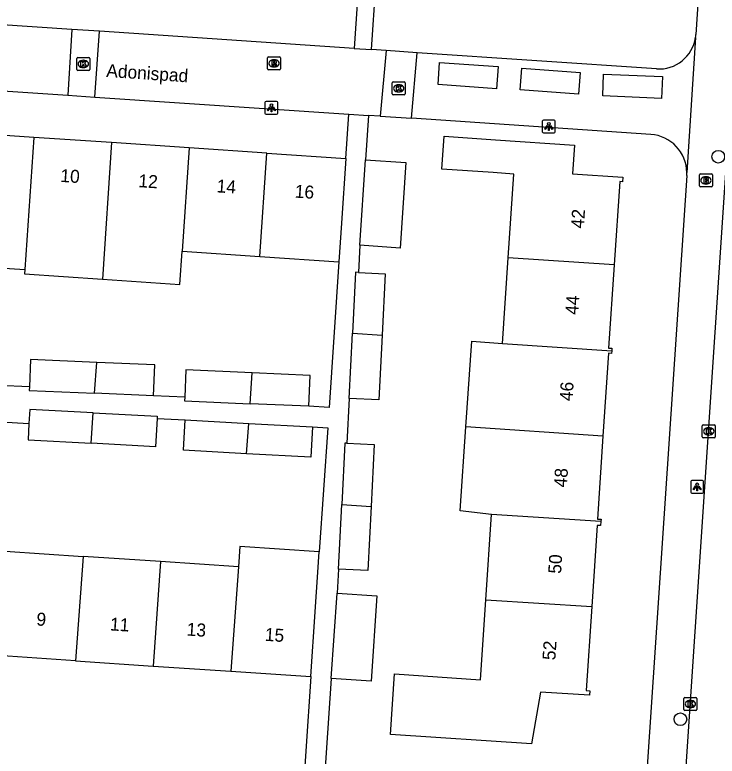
# Model space of a CAD drawing. Extents: x 161848 to 162726, y 385382 to 386521.
# Drawn here: x 162081 to 162135.2, y 385812.1 to 385869.2 of the extents above; entities that cross this region are included whole.
import ezdxf

# ---------------------------------------------------------------- set-up
doc = ezdxf.new("R2010")
doc.units = 0
for name, color, linetype in [('IMGEO_Boom', 7, 'Continuous'), ('IMGEO_Brandkraan', 7, 'Continuous'), ('IMGEO_Kolk', 7, 'Continuous'), ('IMGEO_Lichtpunt', 7, 'Continuous'), ('IMGEO_Openbare_ruimte_label', 7, 'Continuous'), ('IMGEO_Pand', 7, 'Continuous'), ('IMGEO_Pand_nummerreeks', 7, 'Continuous'), ('IMGEO_Parkeervlak_open', 7, 'Continuous'), ('IMGEO_Rijbaan_lokaal_open', 7, 'Continuous'), ('IMGEO_Rioolput', 7, 'Continuous'), ('IMGEO_Voetpad_open', 7, 'Continuous'), ('IMGEO_Woonerf_open', 7, 'Continuous')]:
    doc.layers.add(name, color=color, linetype=linetype)

msp = doc.modelspace()

# ---------------------------------------------------------------- linework, layer by layer
at = {"layer": 'IMGEO_Boom'}
for centre in [(162135.242, 385858.291), (162132.321, 385814.921)]:
    msp.add_circle(centre, 0.489, dxfattribs=at)
at = {"layer": 'IMGEO_Brandkraan'}
for p, q in [((162133.785, 385856.036), (162133.785, 385856.888)), ((162133.86, 385856.962), (162134.712, 385856.962)), ((162134.273, 385856.742), (162134.298, 385856.742)), ((162134.786, 385856.888), (162134.786, 385856.036)), ((162134.296, 385856.182), (162134.271, 385856.182)), ((162134.712, 385855.962), (162133.86, 385855.962))]:
    msp.add_line(p, q, dxfattribs=at)
for points in [[(162133.785, 385856.036), (162133.785, 385856.888)], [(162133.86, 385856.962), (162134.712, 385856.962)], [(162134.133, 385856.662), (162134.133, 385856.262), (162134.346, 385856.262)], [(162134.364, 385856.662), (162134.133, 385856.662)], [(162134.312, 385856.581), (162134.258, 385856.581), (162134.258, 385856.505)], [(162134.786, 385856.888), (162134.786, 385856.036)], [(162134.258, 385856.505), (162134.311, 385856.505)], [(162134.32, 385856.429), (162134.258, 385856.429), (162134.258, 385856.348)], [(162134.258, 385856.348), (162134.32, 385856.348)], [(162134.712, 385855.962), (162133.86, 385855.962)]]:
    msp.add_lwpolyline(points, dxfattribs=at)
for centre, radius, start, end in [((162133.862, 385856.886), 0.0765, 91.552, 178.448), ((162133.862, 385856.886), 0.0765, 91.552, 178.448), ((162134.313, 385856.543), 0.0379, 267.8285, 90.9355), ((162134.368, 385856.517), 0.145, 59.4692, 91.5367), ((162134.393, 385856.564), 0.0922, 285.5137, 58.1501), ((162134.71, 385856.886), 0.0765, 1.552, 88.448), ((162134.71, 385856.886), 0.0765, 1.552, 88.448), ((162133.862, 385856.038), 0.0765, 181.552, 268.448), ((162133.862, 385856.038), 0.0765, 181.552, 268.448), ((162134.321, 385856.388), 0.0404, 269.8759, 90.5077), ((162134.352, 385856.513), 0.251, 268.6676, 293.5347), ((162134.398, 385856.372), 0.105, 301.3115, 78.989), ((162134.71, 385856.038), 0.0765, 271.552, 358.448), ((162134.71, 385856.038), 0.0765, 271.552, 358.448)]:
    msp.add_arc(centre, radius, start, end, dxfattribs=at)
for centre, major_axis, ratio, start_param, end_param in [((162134.272, 385856.462), (-0.387, 0.002), 0.722429, 4.712389, 7.853982), ((162134.297, 385856.462), (-0.39, 0.002), 0.717154, 1.570796, 4.712389)]:
    msp.add_ellipse(centre, major_axis=major_axis, ratio=ratio, start_param=start_param, end_param=end_param, dxfattribs=at)
at = {"layer": 'IMGEO_Kolk'}
for p, q in [((162085.78, 385865.022), (162085.78, 385865.874)), ((162085.855, 385865.948), (162086.707, 385865.948)), ((162086.268, 385865.728), (162086.293, 385865.728)), ((162086.781, 385865.874), (162086.781, 385865.022)), ((162086.291, 385865.168), (162086.266, 385865.168)), ((162086.707, 385864.948), (162085.855, 385864.948)), ((162110.098, 385863.135), (162110.098, 385863.987)), ((162110.173, 385864.061), (162111.025, 385864.061)), ((162111.099, 385863.987), (162111.099, 385863.135)), ((162110.586, 385863.841), (162110.611, 385863.841)), ((162111.025, 385863.061), (162110.173, 385863.061)), ((162110.609, 385863.281), (162110.584, 385863.281)), ((162134.009, 385836.687), (162134.009, 385837.539)), ((162134.084, 385837.613), (162134.936, 385837.613)), ((162134.497, 385837.393), (162134.522, 385837.393)), ((162135.01, 385837.539), (162135.01, 385836.687)), ((162134.936, 385836.613), (162134.084, 385836.613)), ((162134.52, 385836.833), (162134.495, 385836.833)), ((162132.667, 385816.59), (162133.519, 385816.59)), ((162132.592, 385815.664), (162132.592, 385816.516)), ((162133.08, 385816.37), (162133.105, 385816.37)), ((162133.593, 385816.516), (162133.593, 385815.664)), ((162133.519, 385815.59), (162132.667, 385815.59)), ((162133.103, 385815.81), (162133.078, 385815.81))]:
    msp.add_line(p, q, dxfattribs=at)
for points in [[(162085.78, 385865.022), (162085.78, 385865.874)], [(162085.855, 385865.948), (162086.707, 385865.948)], [(162086.781, 385865.874), (162086.781, 385865.022)], [(162086.101, 385865.648), (162086.224, 385865.648), (162086.224, 385865.497), (162086.354, 385865.648), (162086.518, 385865.648), (162086.372, 385865.497), (162086.525, 385865.248), (162086.373, 385865.248), (162086.288, 385865.412), (162086.224, 385865.345), (162086.224, 385865.248), (162086.101, 385865.248), (162086.101, 385865.648)], [(162086.707, 385864.948), (162085.855, 385864.948)], [(162110.098, 385863.135), (162110.098, 385863.987)], [(162110.173, 385864.061), (162111.025, 385864.061)], [(162111.099, 385863.987), (162111.099, 385863.135)], [(162110.419, 385863.761), (162110.542, 385863.761), (162110.542, 385863.61), (162110.672, 385863.761), (162110.836, 385863.761), (162110.69, 385863.61), (162110.843, 385863.361), (162110.691, 385863.361), (162110.606, 385863.525), (162110.542, 385863.458), (162110.542, 385863.361), (162110.419, 385863.361), (162110.419, 385863.761)], [(162111.025, 385863.061), (162110.173, 385863.061)], [(162134.009, 385836.687), (162134.009, 385837.539)], [(162134.084, 385837.613), (162134.936, 385837.613)], [(162134.33, 385837.313), (162134.453, 385837.313), (162134.453, 385837.162), (162134.583, 385837.313), (162134.747, 385837.313), (162134.601, 385837.162), (162134.754, 385836.913), (162134.602, 385836.913), (162134.517, 385837.077), (162134.453, 385837.01), (162134.453, 385836.913), (162134.33, 385836.913), (162134.33, 385837.313)], [(162135.01, 385837.539), (162135.01, 385836.687)], [(162134.936, 385836.613), (162134.084, 385836.613)], [(162132.667, 385816.59), (162133.519, 385816.59)], [(162132.592, 385815.664), (162132.592, 385816.516)], [(162132.913, 385816.29), (162133.036, 385816.29), (162133.036, 385816.139), (162133.166, 385816.29), (162133.33, 385816.29), (162133.184, 385816.139), (162133.337, 385815.89), (162133.185, 385815.89), (162133.1, 385816.054), (162133.036, 385815.987), (162133.036, 385815.89), (162132.913, 385815.89), (162132.913, 385816.29)], [(162133.593, 385816.516), (162133.593, 385815.664)], [(162133.519, 385815.59), (162132.667, 385815.59)]]:
    msp.add_lwpolyline(points, dxfattribs=at)
for centre, start, end in [((162085.857, 385865.872), 91.552, 178.448), ((162085.857, 385865.872), 91.552, 178.448), ((162086.705, 385865.872), 1.552, 88.448), ((162086.705, 385865.872), 1.552, 88.448), ((162085.857, 385865.024), 181.552, 268.448), ((162085.857, 385865.024), 181.552, 268.448), ((162086.705, 385865.024), 271.552, 358.448), ((162086.705, 385865.024), 271.552, 358.448), ((162110.175, 385863.985), 91.552, 178.448), ((162110.175, 385863.985), 91.552, 178.448), ((162111.023, 385863.985), 1.552, 88.448), ((162111.023, 385863.985), 1.552, 88.448), ((162110.175, 385863.137), 181.552, 268.448), ((162110.175, 385863.137), 181.552, 268.448), ((162111.023, 385863.137), 271.552, 358.448), ((162111.023, 385863.137), 271.552, 358.448), ((162134.086, 385837.537), 91.552, 178.448), ((162134.086, 385837.537), 91.552, 178.448), ((162134.934, 385837.537), 1.552, 88.448), ((162134.934, 385837.537), 1.552, 88.448), ((162134.086, 385836.689), 181.552, 268.448), ((162134.086, 385836.689), 181.552, 268.448), ((162134.934, 385836.689), 271.552, 358.448), ((162134.934, 385836.689), 271.552, 358.448), ((162132.669, 385816.514), 91.552, 178.448), ((162132.669, 385816.514), 91.552, 178.448), ((162133.517, 385816.514), 1.552, 88.448), ((162133.517, 385816.514), 1.552, 88.448), ((162132.669, 385815.666), 181.552, 268.448), ((162132.669, 385815.666), 181.552, 268.448), ((162133.517, 385815.666), 271.552, 358.448), ((162133.517, 385815.666), 271.552, 358.448)]:
    msp.add_arc(centre, 0.0765, start, end, dxfattribs=at)
for centre, major_axis, ratio, start_param, end_param in [((162086.267, 385865.448), (-0.387, 0.002), 0.722429, 4.712389, 7.853982), ((162086.292, 385865.448), (-0.39, 0.002), 0.717154, 1.570796, 4.712389), ((162110.585, 385863.561), (-0.387, 0.002), 0.722429, 4.712389, 7.853982), ((162110.61, 385863.561), (-0.39, 0.002), 0.717154, 1.570796, 4.712389), ((162134.496, 385837.113), (-0.387, 0.002), 0.722429, 4.712389, 7.853982), ((162134.521, 385837.113), (-0.39, 0.002), 0.717154, 1.570796, 4.712389), ((162133.079, 385816.09), (-0.387, 0.002), 0.722429, 4.712389, 7.853982), ((162133.104, 385816.09), (-0.39, 0.002), 0.717154, 1.570796, 4.712389)]:
    msp.add_ellipse(centre, major_axis=major_axis, ratio=ratio, start_param=start_param, end_param=end_param, dxfattribs=at)
at = {"layer": 'IMGEO_Lichtpunt'}
for p, q in [((162100.284, 385862.463), (162100.284, 385861.656)), ((162100.284, 385862.463), (162100.284, 385861.656)), ((162101.186, 385862.558), (162100.378, 385862.558)), ((162101.186, 385862.558), (162100.378, 385862.558)), ((162101.28, 385861.656), (162101.28, 385862.463)), ((162101.28, 385861.656), (162101.28, 385862.463)), ((162100.378, 385861.562), (162101.186, 385861.562)), ((162100.378, 385861.562), (162101.186, 385861.562)), ((162122.575, 385861.119), (162121.767, 385861.119)), ((162122.575, 385861.119), (162121.767, 385861.119)), ((162121.673, 385861.024), (162121.673, 385860.217)), ((162121.673, 385861.024), (162121.673, 385860.217)), ((162122.669, 385860.217), (162122.669, 385861.024)), ((162122.669, 385860.217), (162122.669, 385861.024)), ((162121.767, 385860.123), (162122.575, 385860.123)), ((162121.767, 385860.123), (162122.575, 385860.123)), ((162133.114, 385833.238), (162133.114, 385832.431)), ((162133.114, 385833.238), (162133.114, 385832.431)), ((162134.016, 385833.333), (162133.208, 385833.333)), ((162134.016, 385833.333), (162133.208, 385833.333)), ((162134.11, 385832.431), (162134.11, 385833.238)), ((162134.11, 385832.431), (162134.11, 385833.238)), ((162133.208, 385832.337), (162134.016, 385832.337)), ((162133.208, 385832.337), (162134.016, 385832.337))]:
    msp.add_line(p, q, dxfattribs=at)
for points in [[(162100.658, 385862.127), (162100.697, 385862.099), (162100.509, 385861.837), (162100.471, 385861.864), (162100.658, 385862.127)], [(162100.76, 385862.079), (162100.807, 385862.079), (162100.807, 385861.757), (162100.76, 385861.757), (162100.76, 385862.079)], [(162100.87, 385862.099), (162100.908, 385862.126), (162101.095, 385861.864), (162101.056, 385861.836), (162100.87, 385862.099)], [(162122.047, 385860.688), (162122.086, 385860.66), (162121.898, 385860.398), (162121.86, 385860.425), (162122.047, 385860.688)], [(162122.149, 385860.64), (162122.196, 385860.64), (162122.196, 385860.318), (162122.149, 385860.318), (162122.149, 385860.64)], [(162122.259, 385860.66), (162122.297, 385860.687), (162122.484, 385860.425), (162122.445, 385860.397), (162122.259, 385860.66)], [(162133.488, 385832.902), (162133.527, 385832.874), (162133.339, 385832.612), (162133.301, 385832.639), (162133.488, 385832.902)], [(162133.59, 385832.854), (162133.637, 385832.854), (162133.637, 385832.532), (162133.59, 385832.532), (162133.59, 385832.854)], [(162133.7, 385832.874), (162133.738, 385832.901), (162133.925, 385832.639), (162133.886, 385832.611), (162133.7, 385832.874)]]:
    msp.add_lwpolyline(points, dxfattribs=at)
for centre in [(162100.783, 385862.261), (162122.172, 385860.822), (162133.613, 385833.036)]:
    msp.add_circle(centre, 0.0994, dxfattribs=at)
for centre, start, end in [((162100.378, 385862.463), 90, 180), ((162100.378, 385862.463), 90, 180), ((162101.186, 385862.463), 0, 90), ((162101.186, 385862.463), 0, 90), ((162100.378, 385861.656), 180, 270), ((162100.378, 385861.656), 180, 270), ((162101.186, 385861.656), 270, 0), ((162101.186, 385861.656), 270, 360), ((162121.767, 385861.024), 90, 180), ((162121.767, 385861.024), 90, 180), ((162122.575, 385861.024), 0, 90), ((162122.575, 385861.024), 0, 90), ((162121.767, 385860.217), 180, 270), ((162121.767, 385860.217), 180, 270), ((162122.575, 385860.217), 270, 0), ((162122.575, 385860.217), 270, 360), ((162133.208, 385833.238), 90, 180), ((162133.208, 385833.238), 90, 180), ((162134.016, 385833.238), 0, 90), ((162134.016, 385833.238), 0, 90), ((162133.208, 385832.431), 180, 270), ((162133.208, 385832.431), 180, 270), ((162134.016, 385832.431), 270, 0), ((162134.016, 385832.431), 270, 360)]:
    msp.add_arc(centre, 0.0946, start, end, dxfattribs=at)
at = {"layer": 'IMGEO_Pand'}
for points in [[(162082.474, 385859.778), (162076.49, 385860.18)], [(162082.474, 385859.778), (162081.768, 385849.589)], [(162088.459, 385859.376), (162082.474, 385859.778)], [(162119.052, 385850.493), (162119.487, 385856.938), (162117.881, 385857.068), (162113.922, 385857.335), (162114.093, 385859.869), (162118.052, 385859.602), (162124.146, 385859.191), (162123.996, 385856.969), (162127.882, 385856.707), (162127.858, 385856.357), (162127.639, 385856.372), (162127.206, 385849.949)], [(162088.459, 385859.376), (162087.748, 385848.849)], [(162094.445, 385858.974), (162088.459, 385859.376)], [(162094.445, 385858.974), (162093.903, 385851.003)], [(162100.429, 385858.572), (162094.445, 385858.974)], [(162099.901, 385850.6), (162100.429, 385858.572)], [(162100.429, 385858.572), (162106.528, 385858.162)], [(162106.528, 385858.162), (162106.193, 385853.174), (162105.993, 385850.191)], [(162108.047, 385858.047), (162111.16, 385857.837), (162110.717, 385851.252), (162107.604, 385851.462)], [(162107.604, 385851.462), (162108.047, 385858.047)], [(162087.748, 385848.849), (162093.729, 385848.442), (162093.903, 385851.003)], [(162093.903, 385851.003), (162099.901, 385850.6)], [(162099.901, 385850.6), (162105.993, 385850.191)], [(162118.607, 385843.898), (162119.052, 385850.493)], [(162127.206, 385849.949), (162119.052, 385850.493)], [(162075.787, 385849.99), (162081.768, 385849.589)], [(162127.206, 385849.949), (162126.773, 385843.539), (162127.035, 385843.521), (162127.022, 385843.321)], [(162081.768, 385849.589), (162081.745, 385849.257), (162087.748, 385848.849)], [(162107.498, 385849.368), (162107.276, 385849.379), (162107.039, 385844.691)], [(162107.498, 385849.368), (162109.552, 385849.264), (162109.313, 385844.535)], [(162106.785, 385839.656), (162107.039, 385844.691)], [(162109.313, 385844.535), (162109.06, 385839.541), (162106.785, 385839.656)], [(162107.039, 385844.691), (162109.313, 385844.535)], [(162115.785, 385837.456), (162116.231, 385844.062), (162118.607, 385843.898)], [(162118.607, 385843.898), (162127.022, 385843.321)], [(162127.022, 385843.321), (162127.008, 385843.117), (162126.779, 385843.133), (162126.348, 385836.746)], [(162087.315, 385842.431), (162082.219, 385842.655), (162082.126, 385840.55)], [(162087.155, 385840.052), (162087.315, 385842.431)], [(162091.696, 385839.852), (162091.801, 385842.234), (162087.315, 385842.431)], [(162099.307, 385841.627), (162094.189, 385841.851), (162094.096, 385839.746)], [(162099.149, 385839.247), (162099.307, 385841.627)], [(162103.666, 385839.048), (162103.771, 385841.43), (162099.307, 385841.627)], [(162082.126, 385840.55), (162082.114, 385840.273), (162087.155, 385840.052)], [(162091.696, 385839.852), (162087.155, 385840.052)], [(162094.096, 385839.746), (162094.084, 385839.469), (162099.149, 385839.247)], [(162103.666, 385839.048), (162099.149, 385839.247)], [(162087.05, 385838.538), (162082.147, 385838.8), (162082.09, 385837.733)], [(162086.882, 385836.195), (162087.05, 385838.538)], [(162087.05, 385838.538), (162091.974, 385838.274), (162091.965, 385838.111)], [(162082.09, 385837.733), (162082.021, 385836.456), (162086.882, 385836.195)], [(162091.965, 385838.111), (162091.849, 385835.929), (162086.882, 385836.195)], [(162098.875, 385835.39), (162093.995, 385835.652), (162094.121, 385837.996)], [(162094.121, 385837.996), (162099.045, 385837.733)], [(162098.875, 385835.39), (162099.045, 385837.733)], [(162099.045, 385837.733), (162103.948, 385837.47)], [(162103.948, 385837.47), (162103.823, 385835.125), (162098.875, 385835.39)], [(162117.764, 385830.715), (162115.348, 385830.978), (162115.785, 385837.456)], [(162126.348, 385836.746), (162115.785, 385837.456)], [(162126.348, 385836.746), (162125.917, 385830.353), (162126.198, 385830.334), (162126.186, 385830.156)], [(162106.611, 385836.205), (162106.44, 385836.214), (162106.201, 385831.482)], [(162106.611, 385836.205), (162108.716, 385836.099), (162108.475, 385831.332)], [(162105.949, 385826.491), (162106.201, 385831.482)], [(162106.201, 385831.482), (162108.475, 385831.332)], [(162108.475, 385831.332), (162108.224, 385826.376), (162105.949, 385826.491)], [(162117.319, 385824.116), (162117.764, 385830.715)], [(162126.186, 385830.156), (162117.764, 385830.715)], [(162126.186, 385830.156), (162126.165, 385829.848), (162125.909, 385829.866), (162125.486, 385823.602)], [(162104.473, 385827.813), (162098.355, 385828.224), (162098.242, 385826.665)], [(162080.253, 385827.873), (162086.259, 385827.47)], [(162086.259, 385827.47), (162085.684, 385819.421)], [(162092.238, 385827.068), (162086.259, 385827.47)], [(162103.827, 385818.202), (162104.162, 385823.191), (162104.368, 385826.253), (162104.473, 385827.813)], [(162092.238, 385827.068), (162091.665, 385819.019)], [(162098.242, 385826.665), (162092.238, 385827.068)], [(162098.242, 385826.665), (162097.658, 385818.617)], [(162105.842, 385824.649), (162108.912, 385824.444), (162108.472, 385817.858), (162105.402, 385818.063)], [(162105.402, 385818.063), (162105.842, 385824.649)], [(162125.486, 385823.602), (162125.049, 385817.133), (162125.325, 385817.115), (162125.302, 385816.764), (162121.542, 385817.017), (162120.835, 385813.009), (162109.956, 385813.743), (162110.271, 385818.41), (162116.904, 385817.962), (162117.319, 385824.116)], [(162117.319, 385824.116), (162125.486, 385823.602)], [(162085.684, 385819.421), (162079.688, 385819.824)], [(162085.684, 385819.421), (162091.665, 385819.019)], [(162091.665, 385819.019), (162097.658, 385818.617)], [(162097.658, 385818.617), (162103.827, 385818.202)]]:
    msp.add_lwpolyline(points, dxfattribs=at)
at = {"layer": 'IMGEO_Parkeervlak_open'}
for points in [[(162118.14, 385863.536), (162113.631, 385863.847), (162113.749, 385865.555), (162118.258, 385865.244), (162118.14, 385863.536)], [(162119.973, 385863.442), (162120.097, 385865.126), (162124.59, 385864.795), (162124.466, 385863.111), (162119.973, 385863.442)], [(162126.401, 385864.664), (162130.937, 385864.465), (162130.863, 385862.775), (162126.327, 385862.974), (162126.401, 385864.664)]]:
    msp.add_lwpolyline(points, dxfattribs=at)
at = {"layer": 'IMGEO_Rijbaan_lokaal_open'}
msp.add_lwpolyline([(162143.703, 385975.556), (162132.307, 385804.741)], dxfattribs=at)
at = {"layer": 'IMGEO_Rioolput'}
for p, q in [((162100.485, 385865.066), (162100.485, 385865.918)), ((162100.56, 385865.992), (162101.412, 385865.992)), ((162100.973, 385865.772), (162100.998, 385865.772)), ((162101.486, 385865.918), (162101.486, 385865.066)), ((162100.996, 385865.212), (162100.971, 385865.212)), ((162101.412, 385864.992), (162100.56, 385864.992))]:
    msp.add_line(p, q, dxfattribs=at)
for points in [[(162100.485, 385865.066), (162100.485, 385865.918)], [(162100.56, 385865.992), (162101.412, 385865.992)], [(162101.074, 385865.69), (162100.822, 385865.692), (162100.822, 385865.292)], [(162101.486, 385865.918), (162101.486, 385865.066)], [(162100.822, 385865.292), (162100.946, 385865.292), (162100.946, 385865.454), (162100.957, 385865.454)], [(162101, 385865.611), (162100.946, 385865.611), (162100.946, 385865.53)], [(162100.946, 385865.53), (162100.998, 385865.53)], [(162101.004, 385865.425), (162101.075, 385865.292), (162101.215, 385865.292), (162101.15, 385865.418)], [(162101.412, 385864.992), (162100.56, 385864.992)]]:
    msp.add_lwpolyline(points, dxfattribs=at)
for centre, radius, start, end in [((162100.562, 385865.916), 0.0765, 91.552, 178.448), ((162100.562, 385865.916), 0.0765, 91.552, 178.448), ((162101.073, 385865.58), 0.109, 350.3612, 89.416), ((162101.41, 385865.916), 0.0765, 1.552, 88.448), ((162101.41, 385865.916), 0.0765, 1.552, 88.448), ((162100.956, 385865.401), 0.0533, 26.0293, 88.6989), ((162100.982, 385865.719), 0.19, 274.7715, 282.9687), ((162101.006, 385865.515), 0.0964, 77.0061, 93.1865), ((162101.02, 385865.572), 0.0378, 276.6634, 79.6772), ((162101.071, 385865.58), 0.112, 277.5842, 350.9817), ((162101.055, 385865.365), 0.108, 29.5134, 73.7905), ((162100.562, 385865.068), 0.0765, 181.552, 268.448), ((162100.562, 385865.068), 0.0765, 181.552, 268.448), ((162101.41, 385865.068), 0.0765, 271.552, 358.448), ((162101.41, 385865.068), 0.0765, 271.552, 358.448)]:
    msp.add_arc(centre, radius, start, end, dxfattribs=at)
for centre, major_axis, ratio, start_param, end_param in [((162100.972, 385865.492), (-0.387, 0.002), 0.722429, 4.712389, 7.853982), ((162100.997, 385865.492), (-0.39, 0.002), 0.717154, 1.570796, 4.712389)]:
    msp.add_ellipse(centre, major_axis=major_axis, ratio=ratio, start_param=start_param, end_param=end_param, dxfattribs=at)
at = {"layer": 'IMGEO_Voetpad_open'}
for points in [[(162136.757, 385917.011), (162133.513, 385867.72)], [(162108.503, 385866.546), (162109.836, 385886.33)], [(162107.935, 385878.155), (162107.159, 385866.636)], [(162133.486, 385867.478), (162132.815, 385857.068)], [(162107.159, 385866.636), (162108.503, 385866.546)], [(162106.528, 385858.162), (162106.758, 385861.576)], [(162106.758, 385861.576), (162108.278, 385861.474)], [(162108.278, 385861.474), (162108.047, 385858.047)], [(162132.809, 385856.832), (162129.533, 385807.812)], [(162107.604, 385851.462), (162107.498, 385849.368)], [(162105.993, 385850.191), (162105.229, 385838.942), (162103.666, 385839.048)], [(162082.126, 385840.55), (162079.727, 385840.656)], [(162094.096, 385839.746), (162091.696, 385839.852)], [(162106.785, 385839.656), (162106.611, 385836.205)], [(162079.93, 385837.849), (162082.09, 385837.733)], [(162091.965, 385838.111), (162094.121, 385837.996)], [(162103.948, 385837.47), (162105.123, 385837.39), (162104.473, 385827.813)], [(162105.949, 385826.491), (162105.842, 385824.649)], [(162103.827, 385818.202), (162103.056, 385806.692)], [(162105.402, 385818.063), (162104.633, 385806.586)]]:
    msp.add_lwpolyline(points, dxfattribs=at)
for centre, radius, start, end in [((162130.536, 385867.93), 2.984, 351.2957, 355.972), ((162130.491, 385857.009), 2.324, 355.6328, 1.4545)]:
    msp.add_arc(centre, radius, start, end, dxfattribs=at)
at = {"layer": 'IMGEO_Woonerf_open'}
for points in [[(162085.397, 385868.102), (162061.295, 385869.726)], [(162085.397, 385868.102), (162085.081, 385863.036)], [(162087.531, 385867.959), (162085.397, 385868.102)], [(162087.167, 385862.895), (162087.531, 385867.959)], [(162107.159, 385866.636), (162087.531, 385867.959)], [(162109.641, 385866.469), (162108.503, 385866.546)], [(162109.641, 385866.469), (162109.174, 385861.414)], [(162112.02, 385866.308), (162109.641, 385866.469)], [(162111.595, 385861.251), (162112.02, 385866.308)], [(162130.472, 385865.065), (162112.02, 385866.308)], [(162060.825, 385864.668), (162085.081, 385863.036)], [(162085.081, 385863.036), (162087.167, 385862.895)], [(162087.167, 385862.895), (162106.758, 385861.576)], [(162109.174, 385861.414), (162108.278, 385861.474)], [(162109.174, 385861.414), (162111.595, 385861.251)], [(162130.03, 385860.011), (162111.595, 385861.251)]]:
    msp.add_lwpolyline(points, dxfattribs=at)
for centre, radius, start, end in [((162130.667, 385867.91), 2.852, 266.0717, 351.2896), ((162129.831, 385857.033), 2.985, 0.6708, 86.1691)]:
    msp.add_arc(centre, radius, start, end, dxfattribs=at)

# ---------------------------------------------------------------- texts
at = {"layer": 'IMGEO_Openbare_ruimte_label'}
msp.add_text('Adonispad', height=1, rotation=356.1593, dxfattribs=at).set_placement((162088.03, 385864.447))
at = {"layer": 'IMGEO_Pand_nummerreeks'}
for s, rotation, p in [('10', 356.1572, (162084.488, 385856.355)), ('12', 356.1572, (162090.507, 385855.95)), ('14', 356.1572, (162096.536, 385855.546)), ('16', 356.1572, (162102.562, 385855.141)), ('42', 86.2244, (162124.873, 385852.733)), ('44', 86.2236, (162124.433, 385846.079)), ('46', 86.2236, (162123.994, 385839.422)), ('48', 86.2236, (162123.556, 385832.769)), ('50', 86.2236, (162123.116, 385826.112)), ('9', 356.1547, (162082.639, 385822.152)), ('11', 356.1547, (162088.317, 385821.771)), ('13', 356.1547, (162094.227, 385821.373)), ('15', 356.1555, (162100.251, 385820.968)), ('52', 86.2236, (162122.676, 385819.45))]:
    msp.add_text(s, height=1, rotation=rotation, dxfattribs=at).set_placement(p)

doc.saveas('drawing.dxf')
